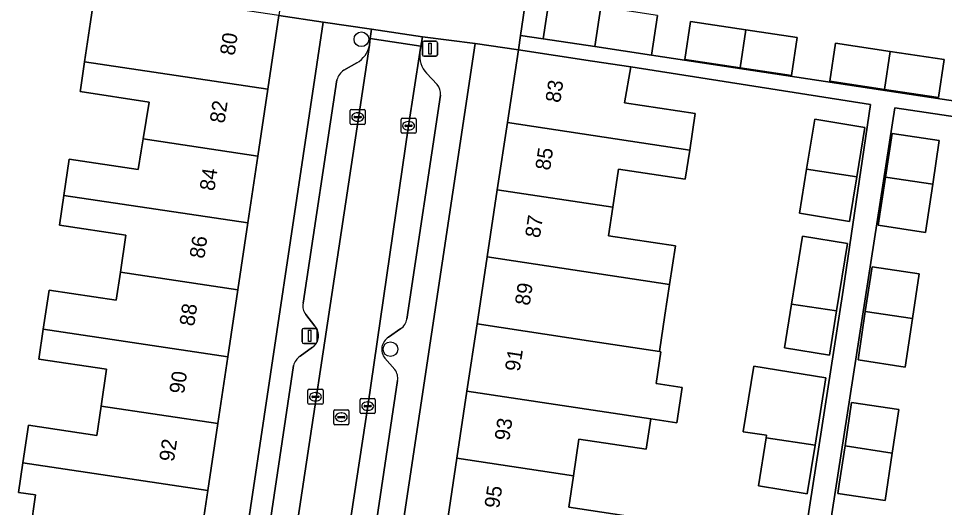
# Model space of a CAD drawing. Extents: x 163008 to 163854, y 382777 to 383982.
# Drawn here: x 163605.7 to 163667.4, y 383336.6 to 383369.2 of the extents above; entities that cross this region are included whole.
import ezdxf

# ---------------------------------------------------------------- set-up
doc = ezdxf.new("R2010")
doc.units = 0
for name, color, linetype in [('IMGEO_Boom', 7, 'Continuous'), ('IMGEO_Erf', 7, 'Continuous'), ('IMGEO_Kolk', 7, 'Continuous'), ('IMGEO_Lichtmast', 7, 'Continuous'), ('IMGEO_Muur', 7, 'Continuous'), ('IMGEO_Pand', 7, 'Continuous'), ('IMGEO_Pand_nummerreeks', 7, 'Continuous'), ('IMGEO_Parkeervlak_open', 7, 'Continuous'), ('IMGEO_Rijbaan_lokaal_open', 7, 'Continuous'), ('IMGEO_Rioolput', 7, 'Continuous'), ('IMGEO_Voetpad_open', 7, 'Continuous')]:
    doc.layers.add(name, color=color, linetype=linetype)

msp = doc.modelspace()

# ---------------------------------------------------------------- linework, layer by layer
at = {"layer": 'IMGEO_Boom'}
for centre in [(163628.572, 383367.813), (163630.508, 383347.184)]:
    msp.add_circle(centre, 0.489, dxfattribs=at)
at = {"layer": 'IMGEO_Erf'}
for points in [[(163641.229, 383382.034), (163639.167, 383368.07), (163640.674, 383367.847), (163641.071, 383370.478)], [(163606.53, 383335.131), (163606.881, 383337.483), (163605.742, 383337.653), (163606.037, 383339.629), (163606.41, 383342.121), (163610.951, 383341.442), (163611.243, 383343.399), (163611.609, 383345.845), (163607.093, 383346.521), (163607.393, 383348.526), (163607.78, 383351.114), (163612.248, 383350.446), (163612.526, 383352.307), (163612.893, 383354.765), (163608.461, 383355.428), (163608.759, 383357.422), (163609.12, 383359.832), (163613.713, 383359.145), (163613.911, 383360.376), (163614.04, 383361.18), (163614.433, 383363.636), (163609.844, 383364.324), (163609.861, 383364.44), (163610.141, 383366.316), (163610.537, 383368.962), (163610.875, 383371.224)], [(163648.296, 383369.39), (163647.899, 383366.759), (163678.827, 383362.061)], [(163655.823, 383319.949), (163660.643, 383351.122), (163662.475, 383363.471), (163646.519, 383365.974), (163646.086, 383363.572), (163650.798, 383362.863), (163650.433, 383360.441), (163650.139, 383358.49), (163645.694, 383359.16), (163645.315, 383356.641), (163645.028, 383354.736), (163649.484, 383354.064), (163649.098, 383351.499), (163648.788, 383349.438), (163648.426, 383347.03), (163648.507, 383347.018), (163648.189, 383344.904), (163649.925, 383344.642), (163649.571, 383342.285), (163647.834, 383342.547), (163647.531, 383340.53), (163643.061, 383341.204), (163642.692, 383338.752), (163642.379, 383336.674), (163646.79, 383336.01)], [(163679.889, 383360.907), (163664.081, 383363.249), (163659.743, 383335.218), (163658.351, 383326.217), (163656.981, 383317.216), (163656.609, 383313.683), (163656.621, 383313.742), (163657.071, 383316.66), (163660.231, 383316.328), (163659.748, 383313.212), (163659.274, 383310.16), (163656.61, 383310.44), (163656.272, 383310.476), (163655.965, 383307.874), (163659.102, 383307.514), (163658.715, 383304.141), (163666.408, 383303.048), (163666.795, 383305.63), (163667.104, 383307.692), (163671.602, 383307.017)]]:
    msp.add_lwpolyline(points, dxfattribs=at)
for points in [[(163626.017, 383368.942), (163623.079, 383369.386), (163622.346, 383364.487), (163621.681, 383360.036), (163621.015, 383355.585), (163620.35, 383351.135), (163619.684, 383346.684), (163619.019, 383342.234), (163618.353, 383337.783), (163617.688, 383333.333), (163617.022, 383328.882), (163616.357, 383324.432), (163615.691, 383319.982), (163615.026, 383315.533), (163614.322, 383310.826), (163617.252, 383310.387)], [(163653.791, 383365.916), (163650.101, 383366.47), (163650.482, 383368.998), (163654.161, 383368.446), (163657.584, 383367.932), (163657.205, 383365.403)], [(163632.912, 383326.513), (163633.585, 383330.983), (163634.258, 383335.452), (163634.931, 383339.922), (163635.604, 383344.391), (163636.277, 383348.861), (163636.95, 383353.33), (163637.623, 383357.8), (163638.296, 383362.27), (163639.024, 383367.102), (163636.157, 383367.519), (163627.364, 383309.04), (163630.216, 383308.611), (163630.891, 383313.093), (163631.566, 383317.573), (163632.239, 383322.043)], [(163663.409, 383364.473), (163659.76, 383365.02), (163660.14, 383367.549), (163663.779, 383367.003), (163667.374, 383366.463), (163666.994, 383363.935)], [(163658.219, 383359.164), (163658.763, 383362.488), (163662.101, 383361.942), (163661.564, 383358.66), (163661.077, 383355.682), (163657.739, 383356.228)], [(163662.992, 383355.428), (163663.475, 383358.634), (163663.914, 383361.543), (163667.051, 383361.071), (163666.613, 383358.163), (163666.129, 383354.957)], [(163657.218, 383350.19), (163657.945, 383354.698), (163660.938, 383354.215), (163660.217, 383349.738), (163659.742, 383346.797), (163656.748, 383347.279)], [(163665.264, 383349.218), (163664.778, 383345.996), (163661.641, 383346.466), (163662.127, 383349.689), (163662.577, 383352.673), (163665.714, 383352.202)], [(163655.519, 383341.29), (163655.546, 383341.459), (163653.994, 383341.693), (163653.996, 383341.709), (163654.696, 383346.051), (163659.503, 383345.276), (163658.781, 383340.798), (163658.26, 383337.566), (163655.003, 383338.091)], [(163663.915, 383340.273), (163663.437, 383337.105), (163660.301, 383337.578), (163660.396, 383338.206), (163660.779, 383340.744), (163661.216, 383343.646), (163664.353, 383343.176)]]:
    msp.add_lwpolyline(points, close=True, dxfattribs=at)
at = {"layer": 'IMGEO_Kolk'}
for p, q in [((163627.828, 383362.21), (163627.828, 383363.062)), ((163627.903, 383363.136), (163628.755, 383363.136)), ((163628.316, 383362.916), (163628.341, 383362.916)), ((163628.829, 383363.062), (163628.829, 383362.21)), ((163628.087, 383362.63), (163628.087, 383362.642)), ((163628.525, 383362.593), (163628.127, 383362.593)), ((163628.13, 383362.679), (163628.528, 383362.679)), ((163628.339, 383362.356), (163628.314, 383362.356)), ((163628.571, 383362.642), (163628.571, 383362.63)), ((163631.212, 383361.628), (163631.212, 383362.48)), ((163631.287, 383362.554), (163632.139, 383362.554)), ((163631.7, 383362.334), (163631.725, 383362.334)), ((163632.213, 383362.48), (163632.213, 383361.628)), ((163628.755, 383362.136), (163627.903, 383362.136)), ((163631.471, 383362.048), (163631.471, 383362.06)), ((163631.909, 383362.011), (163631.511, 383362.011)), ((163631.514, 383362.097), (163631.912, 383362.097)), ((163631.723, 383361.774), (163631.698, 383361.774)), ((163631.955, 383362.06), (163631.955, 383362.048)), ((163632.139, 383361.554), (163631.287, 383361.554)), ((163625.015, 383343.59), (163625.015, 383344.442)), ((163625.09, 383344.516), (163625.942, 383344.516)), ((163626.016, 383344.442), (163626.016, 383343.59)), ((163625.274, 383344.01), (163625.274, 383344.022)), ((163625.712, 383343.973), (163625.314, 383343.973)), ((163625.317, 383344.059), (163625.715, 383344.059)), ((163625.526, 383343.736), (163625.501, 383343.736)), ((163625.503, 383344.296), (163625.528, 383344.296)), ((163625.758, 383344.022), (163625.758, 383344.01)), ((163628.494, 383342.969), (163628.494, 383343.821)), ((163628.569, 383343.895), (163629.421, 383343.895)), ((163629.495, 383343.821), (163629.495, 383342.969)), ((163625.942, 383343.516), (163625.09, 383343.516)), ((163628.753, 383343.389), (163628.753, 383343.401)), ((163629.191, 383343.352), (163628.793, 383343.352)), ((163628.796, 383343.438), (163629.194, 383343.438)), ((163629.005, 383343.115), (163628.98, 383343.115)), ((163628.982, 383343.675), (163629.007, 383343.675)), ((163629.237, 383343.401), (163629.237, 383343.389)), ((163629.421, 383342.895), (163628.569, 383342.895))]:
    msp.add_line(p, q, dxfattribs=at)
for points in [[(163627.828, 383362.21), (163627.828, 383363.062)], [(163627.903, 383363.136), (163628.755, 383363.136)], [(163628.829, 383363.062), (163628.829, 383362.21)], [(163631.212, 383361.628), (163631.212, 383362.48)], [(163631.287, 383362.554), (163632.139, 383362.554)], [(163632.213, 383362.48), (163632.213, 383361.628)], [(163628.755, 383362.136), (163627.903, 383362.136)], [(163632.139, 383361.554), (163631.287, 383361.554)], [(163625.015, 383343.59), (163625.015, 383344.442)], [(163625.09, 383344.516), (163625.942, 383344.516)], [(163626.016, 383344.442), (163626.016, 383343.59)], [(163628.494, 383342.969), (163628.494, 383343.821)], [(163628.569, 383343.895), (163629.421, 383343.895)], [(163629.495, 383343.821), (163629.495, 383342.969)], [(163625.942, 383343.516), (163625.09, 383343.516)], [(163629.421, 383342.895), (163628.569, 383342.895)]]:
    msp.add_lwpolyline(points, dxfattribs=at)
for centre, radius, start, end in [((163627.905, 383363.06), 0.0765, 91.55205, 178.44795), ((163627.905, 383363.06), 0.0765, 91.55205, 178.44795), ((163628.753, 383363.06), 0.0765, 1.55205, 88.44795), ((163628.753, 383363.06), 0.0765, 1.55205, 88.44795), ((163627.905, 383362.212), 0.0765, 181.55205, 268.44795), ((163627.905, 383362.212), 0.0765, 181.55205, 268.44795), ((163628.127, 383362.639), 0.0403, 85.87752, 175.75265), ((163628.124, 383362.629), 0.0366, 178.93798, 274.71019), ((163628.528, 383362.636), 0.043, 264.86636, 352.45326), ((163628.532, 383362.641), 0.0386, 1.73085, 96.63898), ((163628.753, 383362.212), 0.0765, 271.55205, 358.44795), ((163628.753, 383362.212), 0.0765, 271.55205, 358.44795), ((163631.289, 383362.478), 0.0765, 91.55205, 178.44795), ((163631.289, 383362.478), 0.0765, 91.55205, 178.44795), ((163632.137, 383362.478), 0.0765, 1.55205, 88.44795), ((163632.137, 383362.478), 0.0765, 1.55205, 88.44795), ((163631.289, 383361.63), 0.0765, 181.55205, 268.44795), ((163631.289, 383361.63), 0.0765, 181.55205, 268.44795), ((163631.511, 383362.057), 0.0403, 85.87752, 175.75265), ((163631.508, 383362.047), 0.0366, 178.93798, 274.71019), ((163631.912, 383362.054), 0.043, 264.86636, 352.45326), ((163631.916, 383362.059), 0.0386, 1.73085, 96.63898), ((163632.137, 383361.63), 0.0765, 271.55205, 358.44795), ((163632.137, 383361.63), 0.0765, 271.55205, 358.44795), ((163625.092, 383344.44), 0.0765, 91.55205, 178.44795), ((163625.092, 383344.44), 0.0765, 91.55205, 178.44795), ((163625.94, 383344.44), 0.0765, 1.55205, 88.44795), ((163625.94, 383344.44), 0.0765, 1.55205, 88.44795), ((163625.314, 383344.019), 0.0403, 85.87752, 175.75265), ((163625.311, 383344.009), 0.0366, 178.93798, 274.71019), ((163625.715, 383344.016), 0.043, 264.86636, 352.45326), ((163625.719, 383344.021), 0.0386, 1.73085, 96.63898), ((163628.571, 383343.819), 0.0765, 91.55205, 178.44795), ((163628.571, 383343.819), 0.0765, 91.55205, 178.44795), ((163629.419, 383343.819), 0.0765, 1.55205, 88.44795), ((163629.419, 383343.819), 0.0765, 1.55205, 88.44795), ((163625.092, 383343.592), 0.0765, 181.55205, 268.44795), ((163625.092, 383343.592), 0.0765, 181.55205, 268.44795), ((163625.94, 383343.592), 0.0765, 271.55205, 358.44795), ((163625.94, 383343.592), 0.0765, 271.55205, 358.44795), ((163628.793, 383343.398), 0.0403, 85.87752, 175.75265), ((163628.79, 383343.388), 0.0366, 178.93798, 274.71019), ((163629.194, 383343.395), 0.043, 264.86636, 352.45326), ((163629.198, 383343.4), 0.0386, 1.73085, 96.63898), ((163628.571, 383342.971), 0.0765, 181.55205, 268.44795), ((163628.571, 383342.971), 0.0765, 181.55205, 268.44795), ((163629.419, 383342.971), 0.0765, 271.55205, 358.44795), ((163629.419, 383342.971), 0.0765, 271.55205, 358.44795)]:
    msp.add_arc(centre, radius, start, end, dxfattribs=at)
for centre, major_axis, ratio, start_param, end_param in [((163628.315, 383362.636), (-0.387, 0.002), 0.722429, 4.712389, 7.853982), ((163628.34, 383362.636), (-0.39, 0.002), 0.717154, 1.570796, 4.712389), ((163631.699, 383362.054), (-0.387, 0.002), 0.722429, 4.712389, 7.853982), ((163631.724, 383362.054), (-0.39, 0.002), 0.717154, 1.570796, 4.712389), ((163625.502, 383344.016), (-0.387, 0.002), 0.722429, 4.712389, 7.853982), ((163625.527, 383344.016), (-0.39, 0.002), 0.717154, 1.570796, 4.712389), ((163628.981, 383343.395), (-0.387, 0.002), 0.722429, 4.712389, 7.853982), ((163629.006, 383343.395), (-0.39, 0.002), 0.717154, 1.570796, 4.712389)]:
    msp.add_ellipse(centre, major_axis=major_axis, ratio=ratio, start_param=start_param, end_param=end_param, dxfattribs=at)
at = {"layer": 'IMGEO_Lichtmast'}
for p, q in [((163632.645, 383366.785), (163632.645, 383367.585)), ((163632.645, 383367.585), (163632.645, 383366.785)), ((163632.745, 383367.685), (163633.535, 383367.685)), ((163633.535, 383367.685), (163632.745, 383367.685)), ((163633.635, 383367.585), (163633.635, 383366.785)), ((163633.635, 383366.785), (163633.635, 383367.585)), ((163633.535, 383366.685), (163632.745, 383366.685)), ((163632.745, 383366.685), (163633.535, 383366.685)), ((163624.629, 383347.664), (163624.629, 383348.464)), ((163624.629, 383348.464), (163624.629, 383347.664)), ((163624.729, 383348.564), (163625.519, 383348.564)), ((163625.519, 383348.564), (163624.729, 383348.564)), ((163625.619, 383348.464), (163625.619, 383347.664)), ((163625.619, 383347.664), (163625.619, 383348.464)), ((163625.519, 383347.564), (163624.729, 383347.564)), ((163624.729, 383347.564), (163625.519, 383347.564))]:
    msp.add_line(p, q, dxfattribs=at)
for points in [[(163633.065, 383367.56), (163633.215, 383367.56), (163633.215, 383366.81), (163633.065, 383366.81), (163633.065, 383367.56)], [(163625.049, 383348.439), (163625.199, 383348.439), (163625.199, 383347.689), (163625.049, 383347.689), (163625.049, 383348.439)]]:
    msp.add_lwpolyline(points, dxfattribs=at)
for centre, start, end in [((163632.745, 383367.585), 90, 180), ((163632.745, 383367.585), 90, 180), ((163633.535, 383367.585), 0, 90), ((163633.535, 383367.585), 360, 90), ((163632.745, 383366.785), 180, 270), ((163632.745, 383366.785), 180, 270), ((163633.535, 383366.785), 270, 0), ((163633.535, 383366.785), 270, 0), ((163624.729, 383348.464), 90, 180), ((163624.729, 383348.464), 90, 180), ((163625.519, 383348.464), 0, 90), ((163625.519, 383348.464), 360, 90), ((163624.729, 383347.664), 180, 270), ((163624.729, 383347.664), 180, 270), ((163625.519, 383347.664), 270, 0), ((163625.519, 383347.664), 270, 0)]:
    msp.add_arc(centre, 0.1, start, end, dxfattribs=at)
at = {"layer": 'IMGEO_Muur'}
msp.add_lwpolyline([(163639.167, 383368.07), (163641.229, 383382.034)], dxfattribs=at)
at = {"layer": 'IMGEO_Pand'}
for points in [[(163623.079, 383369.386), (163618.134, 383370.125), (163615.699, 383370.49), (163615.718, 383370.614), (163610.892, 383371.336), (163610.875, 383371.224), (163610.537, 383368.962), (163610.141, 383366.316), (163622.346, 383364.487)], [(163644.125, 383367.327), (163644.51, 383369.96), (163641.071, 383370.478), (163640.674, 383367.847)], [(163644.125, 383367.327), (163647.899, 383366.759), (163648.296, 383369.39), (163644.51, 383369.96)], [(163654.161, 383368.446), (163650.482, 383368.998), (163650.101, 383366.47), (163653.791, 383365.916)], [(163654.161, 383368.446), (163653.791, 383365.916), (163657.205, 383365.403), (163657.584, 383367.932)], [(163663.779, 383367.003), (163660.14, 383367.549), (163659.76, 383365.02), (163663.409, 383364.473)], [(163650.433, 383360.441), (163650.798, 383362.863), (163646.086, 383363.572), (163646.519, 383365.974), (163643.969, 383366.357), (163639.024, 383367.102), (163638.296, 383362.27)], [(163663.779, 383367.003), (163663.409, 383364.473), (163666.994, 383363.935), (163667.374, 383366.463)], [(163622.346, 383364.487), (163610.141, 383366.316), (163609.861, 383364.44), (163609.844, 383364.324), (163614.433, 383363.636), (163614.04, 383361.18), (163621.681, 383360.036)], [(163650.433, 383360.441), (163638.296, 383362.27), (163637.623, 383357.8), (163645.315, 383356.641), (163645.694, 383359.16), (163650.139, 383358.49)], [(163658.219, 383359.164), (163661.564, 383358.66), (163662.101, 383361.942), (163658.763, 383362.488)], [(163621.681, 383360.036), (163614.04, 383361.18), (163613.911, 383360.376), (163613.713, 383359.145), (163609.12, 383359.832), (163608.759, 383357.422), (163621.015, 383355.585)], [(163663.475, 383358.634), (163666.613, 383358.163), (163667.051, 383361.071), (163663.914, 383361.543)], [(163658.219, 383359.164), (163657.739, 383356.228), (163661.077, 383355.682), (163661.564, 383358.66)], [(163666.613, 383358.163), (163663.475, 383358.634), (163662.992, 383355.428), (163666.129, 383354.957)], [(163621.015, 383355.585), (163608.759, 383357.422), (163608.461, 383355.428), (163612.893, 383354.765), (163612.526, 383352.307), (163620.35, 383351.135)], [(163649.098, 383351.499), (163649.484, 383354.064), (163645.028, 383354.736), (163645.315, 383356.641), (163637.623, 383357.8), (163636.95, 383353.33)], [(163657.218, 383350.19), (163660.217, 383349.738), (163660.938, 383354.215), (163657.945, 383354.698)], [(163649.098, 383351.499), (163636.95, 383353.33), (163636.277, 383348.861), (163643.975, 383347.701), (163648.426, 383347.03), (163648.788, 383349.438)], [(163662.127, 383349.689), (163665.264, 383349.218), (163665.714, 383352.202), (163662.577, 383352.673)], [(163620.35, 383351.135), (163612.526, 383352.307), (163612.248, 383350.446), (163607.78, 383351.114), (163607.393, 383348.526), (163619.684, 383346.684)], [(163660.217, 383349.738), (163657.218, 383350.19), (163656.748, 383347.279), (163659.742, 383346.797)], [(163665.264, 383349.218), (163662.127, 383349.689), (163661.641, 383346.466), (163664.778, 383345.996)], [(163648.507, 383347.018), (163648.426, 383347.03), (163643.975, 383347.701), (163636.277, 383348.861), (163635.604, 383344.391), (163647.834, 383342.547), (163649.571, 383342.285), (163649.925, 383344.642), (163648.189, 383344.904)], [(163611.243, 383343.399), (163619.019, 383342.234), (163619.684, 383346.684), (163607.393, 383348.526), (163607.093, 383346.521), (163611.609, 383345.845)], [(163655.519, 383341.29), (163658.781, 383340.798), (163659.503, 383345.276), (163654.696, 383346.051), (163653.996, 383341.709), (163653.994, 383341.693), (163655.546, 383341.459)], [(163635.604, 383344.391), (163634.931, 383339.922), (163642.692, 383338.752), (163643.061, 383341.204), (163647.531, 383340.53), (163647.834, 383342.547)], [(163611.243, 383343.399), (163610.951, 383341.442), (163606.41, 383342.121), (163606.037, 383339.629), (163618.353, 383337.783), (163619.019, 383342.234)], [(163660.779, 383340.744), (163663.915, 383340.273), (163664.353, 383343.176), (163661.216, 383343.646)], [(163655.519, 383341.29), (163655.003, 383338.091), (163658.26, 383337.566), (163658.781, 383340.798)], [(163663.915, 383340.273), (163660.779, 383340.744), (163660.396, 383338.206), (163660.301, 383337.578), (163663.437, 383337.105)], [(163618.353, 383337.783), (163606.037, 383339.629), (163605.742, 383337.653), (163606.881, 383337.483), (163606.53, 383335.131), (163609.883, 383334.629), (163609.865, 383334.506), (163617.688, 383333.333)], [(163634.931, 383339.922), (163634.258, 383335.452), (163646.43, 383333.617), (163646.79, 383336.01), (163642.379, 383336.674), (163642.692, 383338.752)]]:
    msp.add_lwpolyline(points, close=True, dxfattribs=at)
at = {"layer": 'IMGEO_Parkeervlak_open'}
for points in [[(163622.309, 383322.342), (163629.103, 383367.415)], [(163632.469, 383366.928), (163631.712, 383362.058), (163628.995, 383343.4), (163625.711, 383321.848)], [(163628.269, 383366.236), (163627.397, 383365.745)], [(163633.612, 383364.792), (163632.917, 383365.551)], [(163626.94, 383365.106), (163624.691, 383350.238)], [(163631.6, 383349.182), (163633.839, 383364.09)], [(163624.864, 383349.496), (163625.48, 383348.718)], [(163630.375, 383347.978), (163631.195, 383348.553)], [(163625.327, 383347.31), (163624.494, 383346.722)], [(163630.804, 383345.83), (163630.139, 383346.579)], [(163624.046, 383346.1), (163620.934, 383325.265)], [(163627.859, 383324.261), (163630.98, 383345.098)]]:
    msp.add_lwpolyline(points, dxfattribs=at)
for centre, radius, start, end in [((163627.405, 383367.732), 1.727, 300.01664, 349.43378), ((163634.144, 383366.712), 1.689, 172.64407, 223.4), ((163628.062, 383364.787), 1.167, 124.75121, 164.10561), ((163632.899, 383364.174), 0.943, 354.90261, 40.93585), ((163625.638, 383350.068), 0.963, 169.8114, 216.43712), ((163624.764, 383348.084), 0.957, 306.06004, 41.53657), ((163630.677, 383349.331), 0.935, 303.64224, 350.80447), ((163630.873, 383347.175), 0.945, 121.79823, 219.0514), ((163625.19, 383345.748), 1.197, 125.56523, 162.90759), ((163630.048, 383345.261), 0.946, 350.07649, 36.96233)]:
    msp.add_arc(centre, radius, start, end, dxfattribs=at)
at = {"layer": 'IMGEO_Rijbaan_lokaal_open'}
for points in [[(163632.535, 383367.35), (163632.635, 383367.982), (163629.256, 383368.49), (163629.166, 383367.856)], [(163625.683, 383321.628), (163625.711, 383321.848), (163628.995, 383343.4), (163631.712, 383362.058), (163632.469, 383366.928), (163632.535, 383367.35), (163629.166, 383367.856), (163629.103, 383367.415), (163622.309, 383322.342), (163622.266, 383322.099)]]:
    msp.add_lwpolyline(points, close=True, dxfattribs=at)
at = {"layer": 'IMGEO_Rioolput'}
for p, q in [((163626.733, 383342.232), (163626.733, 383343.084)), ((163626.808, 383343.158), (163627.66, 383343.158)), ((163627.734, 383343.084), (163627.734, 383342.232)), ((163626.992, 383342.652), (163626.992, 383342.664)), ((163627.43, 383342.615), (163627.032, 383342.615)), ((163627.035, 383342.701), (163627.433, 383342.701)), ((163627.221, 383342.938), (163627.246, 383342.938)), ((163627.476, 383342.664), (163627.476, 383342.652)), ((163627.66, 383342.158), (163626.808, 383342.158)), ((163627.244, 383342.378), (163627.219, 383342.378))]:
    msp.add_line(p, q, dxfattribs=at)
for points in [[(163626.733, 383342.232), (163626.733, 383343.084)], [(163626.808, 383343.158), (163627.66, 383343.158)], [(163627.734, 383343.084), (163627.734, 383342.232)], [(163627.66, 383342.158), (163626.808, 383342.158)]]:
    msp.add_lwpolyline(points, dxfattribs=at)
for centre, radius, start, end in [((163626.81, 383343.082), 0.0765, 91.55205, 178.44795), ((163626.81, 383343.082), 0.0765, 91.55205, 178.44795), ((163627.658, 383343.082), 0.0765, 1.55205, 88.44795), ((163627.658, 383343.082), 0.0765, 1.55205, 88.44795), ((163627.032, 383342.661), 0.0403, 85.87752, 175.75265), ((163627.029, 383342.651), 0.0366, 178.93798, 274.71019), ((163627.433, 383342.658), 0.043, 264.86636, 352.45326), ((163627.437, 383342.663), 0.0386, 1.73085, 96.63898), ((163626.81, 383342.234), 0.0765, 181.55205, 268.44795), ((163626.81, 383342.234), 0.0765, 181.55205, 268.44795), ((163627.658, 383342.234), 0.0765, 271.55205, 358.44795), ((163627.658, 383342.234), 0.0765, 271.55205, 358.44795)]:
    msp.add_arc(centre, radius, start, end, dxfattribs=at)
for centre, major_axis, ratio, start_param, end_param in [((163627.22, 383342.658), (-0.387, 0.002), 0.722429, 4.712389, 7.853982), ((163627.245, 383342.658), (-0.39, 0.002), 0.717154, 1.570796, 4.712389)]:
    msp.add_ellipse(centre, major_axis=major_axis, ratio=ratio, start_param=start_param, end_param=end_param, dxfattribs=at)
at = {"layer": 'IMGEO_Voetpad_open'}
msp.add_lwpolyline([(163633.29, 383395.433), (163627.183, 383396.315), (163626.536, 383392.29), (163625.268, 383384.123), (163624.134, 383376.614), (163623.753, 383374.068), (163623.198, 383370.353), (163623.079, 383369.386), (163626.017, 383368.942), (163629.256, 383368.49), (163632.635, 383367.982), (163636.157, 383367.519), (163639.024, 383367.102), (163639.167, 383368.07), (163641.229, 383382.034), (163642.383, 383389.925), (163642.997, 383393.941), (163636.727, 383394.887), (163633.148, 383370.993), (163629.728, 383371.498)], close=True, dxfattribs=at)
for points in [[(163629.103, 383367.415), (163629.166, 383367.856), (163629.256, 383368.49), (163626.017, 383368.942), (163617.252, 383310.387), (163617.064, 383309.129), (163608.303, 383250.604), (163611.443, 383250.058), (163611.551, 383250.689), (163611.614, 383251.055)], [(163627.135, 383307.514), (163627.364, 383309.04), (163636.157, 383367.519), (163632.635, 383367.982), (163632.535, 383367.35), (163632.469, 383366.928)], [(163678.827, 383362.061), (163647.899, 383366.759), (163644.125, 383367.327), (163640.674, 383367.847), (163639.167, 383368.07), (163639.024, 383367.102), (163643.969, 383366.357), (163646.519, 383365.974), (163662.475, 383363.471), (163660.643, 383351.122), (163655.823, 383319.949)], [(163627.397, 383365.745), (163628.269, 383366.236)], [(163632.917, 383365.551), (163633.612, 383364.792)], [(163624.691, 383350.238), (163626.94, 383365.106)], [(163633.839, 383364.09), (163631.6, 383349.182)], [(163670.912, 383302.373), (163666.408, 383303.048), (163658.715, 383304.141), (163655.215, 383304.543), (163655.602, 383307.916), (163655.965, 383307.874), (163656.272, 383310.476), (163656.089, 383310.495), (163656.609, 383313.683), (163656.981, 383317.216), (163658.351, 383326.217), (163659.743, 383335.218), (163664.081, 383363.249), (163679.889, 383360.907)], [(163625.48, 383348.718), (163624.864, 383349.496)], [(163631.195, 383348.553), (163630.375, 383347.978)], [(163624.494, 383346.722), (163625.327, 383347.31)], [(163630.139, 383346.579), (163630.804, 383345.83)], [(163620.934, 383325.265), (163624.046, 383346.1)], [(163630.98, 383345.098), (163627.859, 383324.261)]]:
    msp.add_lwpolyline(points, dxfattribs=at)
for centre, radius, start, end in [((163627.405, 383367.732), 1.727, 300.01664, 349.43378), ((163634.144, 383366.712), 1.689, 172.64407, 223.4), ((163628.062, 383364.787), 1.167, 124.75121, 164.10561), ((163632.899, 383364.174), 0.943, 354.90261, 40.93585), ((163625.638, 383350.068), 0.963, 169.8114, 216.43712), ((163624.764, 383348.084), 0.957, 306.06004, 41.53657), ((163630.677, 383349.331), 0.935, 303.64224, 350.80447), ((163630.873, 383347.175), 0.945, 121.79823, 219.0514), ((163625.19, 383345.748), 1.197, 125.56523, 162.90759), ((163630.048, 383345.261), 0.946, 350.07649, 36.96233)]:
    msp.add_arc(centre, radius, start, end, dxfattribs=at)

# ---------------------------------------------------------------- texts
at = {"layer": 'IMGEO_Pand_nummerreeks'}
for s, rotation, p in [('80', 81.49752, (163620.128, 383366.692)), ('83', 81.43633, (163641.806, 383363.547)), ('82', 81.49752, (163619.453, 383362.182)), ('85', 81.43633, (163641.128, 383359.047)), ('84', 81.49752, (163618.781, 383357.679)), ('87', 81.43633, (163640.451, 383354.548)), ('86', 81.49507, (163618.107, 383353.175)), ('89', 81.43449, (163639.772, 383350.049)), ('88', 81.49507, (163617.434, 383348.673)), ('91', 81.43449, (163639.112, 383345.661)), ('90', 81.49507, (163616.76, 383344.169)), ('93', 81.43633, (163638.418, 383341.05)), ('92', 81.49507, (163616.085, 383339.659)), ('95', 81.43633, (163637.741, 383336.551))]:
    msp.add_text(s, height=1, rotation=rotation, dxfattribs=at).set_placement(p)

doc.saveas('drawing.dxf')
